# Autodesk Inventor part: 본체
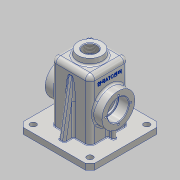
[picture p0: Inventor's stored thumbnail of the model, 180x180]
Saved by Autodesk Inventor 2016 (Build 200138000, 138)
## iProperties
Created: 2018-10
Part Number: 본체
Material: 알루미늄 6061
Document SubType Name: Modeling
Designer: user
Density: 2.7 g/cm^3
Appearance: 알루미늄 - 평지
Mass: 794.228 g
Surface Area: 899.5 cm^2
Volume: 294.158 cm^3
Author: user
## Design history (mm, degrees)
sketch "스케치1"
  geometry: L1 (-60, -60)-(60, -60); L2 (60, -60)-(60, 60); L3 (60, 60)-(-60, 60); L4 (-60, 60)-(-60, -60); L5 (-60, -60)-(60, 60); L6 (60, -60)-(-60, 60); 1 further point
  constraints: 12 end point, 2 midpoint, 2 parallel, 1 horizontal, 1 perpendicular
  dimensions: "d0" = 120 distance of L3.end L2.end; "d1" = 120 distance of L2.end L1.end
extrude "돌출1" new body sketch "스케치1" distance "d2" = 10; taper "d3" = 0 deg
sketch "스케치2"
  geometry: L1 (32.5, -32.5)-(-32.5, -32.5); L2 (-32.5, -32.5)-(-32.5, 32.5); L3 (-32.5, 32.5)-(32.5, 32.5); L4 (32.5, 32.5)-(32.5, -32.5); L5 (32.5, -32.5)-(-32.5, 32.5); L6 (-32.5, -32.5)-(32.5, 32.5); 1 further point
  constraints: 12 end point, 2 midpoint, 2 parallel, 1 horizontal, 1 perpendicular
  dimensions: "d4" = 65 distance of L2.end L3.end; "d5" = 65 distance of L1.end L2.end
extrude "돌출2" join sketch "스케치2" distance "d6" = 100; taper "d7" = 0 deg
feature "쉘1" dims "d8" = 10, "d9" = 5
node "작업 평면1"
sketch "스케치3"
  geometry: C1 r 20 at (0, 0); 1 further point
  constraints: 1 centre point, 1 coincident
  dimensions: "d11" = 40 diameter of C1
extrude "돌출3" join sketch "스케치3" stored distance "d12" = 15; taper "d13" = 7 deg
sketch "스케치4"
  geometry: L1 (10, -27.5)-(10, 92.5) reference; C1 r 27.5 at (-45, 32.5); 2 further points
  constraints: 1 centre point, 1 horizontal alignment, 1 midpoint
  dimensions: "d14" = 55 diameter of C1; "d15" = 55 distance from line of L1 C1.centre
extrude "돌출4" join sketch "스케치4" distance "d16" = 15; taper "d17" = 0 deg
sketch "스케치5"
  geometry: L1 (-32.5, 10)-(-32.5, 110) reference; L2 (60, 10)-(-60, 10) reference; L3 (48, 10)-(32.5, 97.905); L4 (32.5, 10)-(32.5, 110) reference; L5 (60, 0)-(60, 10) reference; L6 (-60, 0)-(-60, 10) reference; L7 (-60, 10)-(-32.5, 10) reference; L8 (-32.5, 10)-(-32.5, 110) reference; L9 (-32.5, 110)-(-21.228, 110) reference; L10 (-21.228, 110)-(-20, 120) reference; L11 (-20, 120)-(20, 120) reference; L12 (20, 120)-(21.228, 110) reference; L13 (21.228, 110)-(32.5, 110) reference; L14 (32.5, 110)-(32.5, 10) reference; L15 (32.5, 10)-(60, 10) reference; L16 (60, 10)-(60, 0) reference; L17 (60, 0)-(27.5, 0) reference; L18 (27.5, 0)-(27.5, 105) reference; L19 (27.5, 105)-(-27.5, 105) reference; L20 (-27.5, 105)-(-27.5, 0) reference; L21 (-27.5, 0)-(-60, 0) reference; 1 further point
  constraints: 2 end point, 2 point on line
  dimensions: "d19" = 10 deg angle of L3 L5; "d20" = 12 horizontal distance of L5.start L3.start
extrude "돌출5" join sketch "스케치5" distance "d21" = 5; taper "d23" = 0 deg; dims "d22" = 5, "d24" = 0
sketch "스케치6"
  geometry: L1 (-60, 0)-(-60, 10) reference; L2 (-60, 10)-(-32.5, 10) reference; L3 (-32.5, 10)-(-32.5, 27.5) reference; L4 (-32.5, 27.5)-(-47.5, 27.5) reference; L5 (-47.5, 27.5)-(-47.5, 82.5) reference; L6 (-47.5, 82.5)-(-32.5, 82.5) reference; L7 (-32.5, 82.5)-(-32.5, 110) reference; L8 (-32.5, 110)-(-21.228, 110) reference; L9 (-21.228, 110)-(-20, 120) reference; L10 (-20, 120)-(20, 120) reference; L11 (20, 120)-(21.228, 110) reference; L12 (21.228, 110)-(32.5, 110) reference; L13 (32.5, 110)-(32.5, 10) reference; L14 (32.5, 10)-(60, 10) reference; L15 (60, 10)-(60, 0) reference; L16 (60, 0)-(27.5, 0) reference; L17 (27.5, 0)-(27.5, 105) reference; L18 (27.5, 105)-(-27.5, 105) reference; L19 (-27.5, 105)-(-27.5, 0) reference; L20 (-27.5, 0)-(-60, 0) reference; L21 (-42.5, 27.5)-(-42.5, 10); 1 further point
  constraints: 2 end point, 2 point on line, 1 perpendicular
  dimensions: "d25" = 15 horizontal distance of L19.end L21.end
feature "리브1" sketch "스케치6" dims "d26" = 1, "d27" = 6, "d28" = 0, "d29" = 0, "d30" = 1, "d31" = 1
sketch "스케치7"
  geometry: L1 (45, -60)-(45, 60) reference; L2 (45, 60)-(55, 60) reference; L3 (55, 60)-(55, -60) reference; L4 (55, -60)-(45, -60) reference; C1 r 27.5 at (0, 0) reference; 2 further points
  constraints: 1 horizontal alignment
  dimensions: "d32" = 21 distance of C1.centre point (-21, 0)
hole "구멍1" sketch "스케치7" at (-21, 0) diameter "d33" = 3.242; stored, may be unused: countersink angle "d37" = 90 deg, drill point angle "d39" = 118 deg; dims "d34" = 8, "d35" = 4, "d36" = 2, "d38" = 10
hole "구멍2" diameter "d42" = 22.835; stored, may be unused: countersink angle "d46" = 90 deg, drill point angle "d48" = 118 deg; dims "d40" = 10, "d41" = 10, "d43" = 50, "d44" = 4, "d45" = 2, "d47" = 59.3
sketch "스케치8"
  geometry: L1 (-5, 32.5)-(-5, 48) reference; L2 (-5, 48)-(5, 48) reference; L3 (5, 48)-(5, 32.5) reference; L4 (5, 32.5)-(32.5, 32.5) reference; L5 (32.5, 32.5)-(32.5, 3) reference; L6 (32.5, 3)-(42.5, 3) reference; L7 (42.5, 3)-(42.5, -3) reference; L8 (42.5, -3)-(32.5, -3) reference; L9 (32.5, -3)-(32.5, -32.5) reference; L10 (32.5, -32.5)-(-32.5, -32.5) reference; L11 (-32.5, -32.5)-(-32.5, 32.5) reference; L12 (-32.5, 32.5)-(-5, 32.5) reference; L13 (-27.5, 27.5)-(-27.5, -27.5) reference; L14 (-27.5, -27.5)-(27.5, -27.5) reference; L15 (27.5, -27.5)-(27.5, 27.5) reference; L16 (27.5, 27.5)-(-27.5, 27.5) reference; L17 (-60, -60)-(-60, 60) reference; L18 (-60, 60)-(60, 60) reference; L19 (60, 60)-(60, -60) reference; L20 (60, -60)-(-60, -60) reference; L21 (-47.5, -47.5)-(47.5, -47.5); L22 (47.5, -47.5)-(47.5, 47.5); L23 (47.5, 47.5)-(-47.5, 47.5); L24 (-47.5, 47.5)-(-47.5, -47.5); L25 (-47.5, -47.5)-(47.5, 47.5); L26 (47.5, -47.5)-(-47.5, 47.5); 5 further points
  constraints: 12 end point, 4 coincident, 2 midpoint, 2 parallel, 1 horizontal, 1 perpendicular
  dimensions: "d49" = 95 distance of L23.end L22.end; "d50" = 95 distance of L22.end L21.end
hole "구멍3" sketch "스케치8" at (-47.5, -47.5), (-47.5, 47.5), (47.5, 47.5), (47.5, -47.5) diameter "d51" = 10; stored, may be unused: countersink angle "d55" = 90 deg, drill point angle "d57" = 118 deg; dims "d52" = 16, "d53" = 4, "d54" = 2, "d56" = 59.3
hole "구멍4" diameter "d60" = 30; stored, may be unused: countersink angle "d64" = 90 deg, drill point angle "d66" = 118 deg; dims "d58" = 10, "d59" = 10, "d61" = 16, "d62" = 35, "d63" = 17, "d65" = 28.55
fillet "모깎기1" dims "d70" = 8
fillet "모깎기2" dims "d71" = 8
fillet "모깎기3" dims "d72" = 3
fillet "모깎기4" dims "d73" = 3
fillet "모깎기5" dims "d74" = 3
fillet "모깎기6" dims "d75" = 3
fillet "모깎기7" dims "d76" = 3
fillet "모깎기8" dims "d77" = 0.3
fillet "모깎기9" dims "d78" = 1
chamfer "모따기1" distance "d79" = 8; stored, may be unused: second distance "d80" = 2, angle "d81" = 45 deg
chamfer "모따기2" distance "d82" = 1; stored, may be unused: second distance "d83" = 2, angle "d84" = 45 deg
sketch "스케치9"
  geometry: L1 (-18, 44.5)-(-18, 4.5) reference; L2 (28.834, 49)-(0, 49) reference; L3 (0, 0)-(0, 49) reference; L4 (28.834, 0)-(0, 0) reference; L5 (91, 0)-(65.166, 0) reference; L6 (91, 0)-(91, 18.5) reference; L7 (76.904, 18.5)-(91, 18.5) reference; L8 (92, -35.5)-(92, -4.123) reference; L9 (102, -35.5)-(92, -35.5) reference; L10 (102, 84.5)-(102, -35.5) reference; L11 (92, 84.5)-(102, 84.5) reference; L12 (92, 53.123)-(92, 84.5) reference; L13 (91, 30.5)-(91, 49) reference; L14 (91, 30.5)-(76.904, 30.5) reference; L15 (91, 49)-(65.166, 49) reference; L16 (0, -8)-(91, -8) reference; C1 r 17.5 at (47, 24.5) reference; A1 r 30.5 centre (47, 24.5) between (65.166, 0) and (76.904, 18.5) reference; A2 r 30.5 centre (47, 24.5) between (28.834, 49) and (28.834, 0) reference; A3 r 30.5 centre (47, 24.5) between (76.904, 30.5) and (65.166, 49) reference; 2 further points
  constraints: 2 horizontal alignment, 3 other
  dimensions: "d85" = 26 distance from line of L1 point (8, 24.5); "d86" = 32.5 distance from line of L16 point (8, 24.5)
feature "엠보싱1" sketch "스케치9" dims "d0" = 120, "d1" = 120, "d87" = 0.5, "d88" = 0
node "솔리드1"
pattern_circular "원형 패턴1" dims angle "d68" = 360 deg
mirror "대칭1"
mirror "대칭2"
node "절단 모서리 투영1"
node "절단 모서리 투영2"
node "절단 모서리 투영3"
node "절단 모서리 투영4"
node "절단 모서리 투영5"
